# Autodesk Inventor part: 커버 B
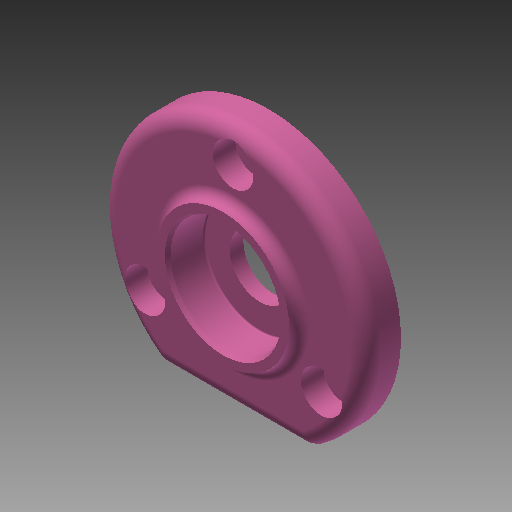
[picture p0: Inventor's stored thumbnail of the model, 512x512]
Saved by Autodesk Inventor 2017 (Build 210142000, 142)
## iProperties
Created: 2020-04
Part Number: 커버 B
Material: 알루미늄 6061
Document SubType Name: Modeling
Designer: mduedu
Density: 1 g/cm^3
Appearance: 분홍색
Author: mduedu
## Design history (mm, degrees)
sketch "스케치1"
  geometry: C1 r 26 at (0, 0); 1 further point
  constraints: 1 centre point, 1 coincident
  dimensions: "d0" = 52 diameter of C1
extrude "돌출1" new body sketch "스케치1" distance "d1" = 7; taper "d2" = 0 deg
sketch "스케치2"
  geometry: L1 (-14.62, -21.5)-(14.62, -21.5); A1 r 26 centre (0, 0) between (-14.62, -21.5) and (14.62, -21.5) reference; 1 further point
  constraints: 2 end point, 2 point on circle, 1 horizontal
  dimensions: "d3" = 21.5 distance from line of L1 point (0, 0)
extrude "돌출2" cut sketch "스케치2" stored distance "d4" = 7; taper "d5" = 0 deg
sketch "스케치6"
  geometry: C1 r 13 at (0, 0); 1 further point
  constraints: 1 centre point, 1 coincident
  dimensions: "d29" = 26 diameter of C1
extrude "돌출5" join sketch "스케치6" distance "d30" = 2; taper "d31" = 0 deg
fillet "모깎기1" dims "d6" = 3
fillet "모깎기2" dims "d7" = 3
fillet "모깎기4" dims "d33" = 2
sketch "스케치3" dims "d8" = 40
  geometry: 3 further points
  constraints: 2 vertical alignment, 1 coincident, 2 other
hole "구멍1" sketch "스케치3" at (0, 20) diameter "d9" = 4.5; stored, may be unused: countersink angle "d13" = 90 deg, drill point angle "d15" = 118 deg; dims "d10" = 6, "d11" = 8, "d12" = 4.4, "d14" = 8
sketch "스케치4"
  geometry: C1 r 14 at (0, 0); 1 further point
  constraints: 1 centre point, 1 coincident
  dimensions: "d19" = 28 diameter of C1
extrude "돌출3" join sketch "스케치4" distance "d20" = 4; taper "d21" = 0 deg
sketch "스케치5"
  geometry: C1 r 12 at (0, 0); 1 further point
  constraints: 1 centre point, 1 coincident
  dimensions: "d22" = 24 diameter of C1
extrude "돌출4" cut sketch "스케치5" distance "d23" = 3; taper "d24" = 0 deg
fillet "모깎기3" dims "d25" = 3
chamfer "모따기1" distance "d26" = 0.5; stored, may be unused: second distance "d27" = 2, angle "d28" = 45 deg
sketch "스케치7"
  geometry: 2 further points
  constraints: 1 coincident
hole "구멍2" sketch "스케치7" at (0, 0) diameter "d34" = 12; stored, may be unused: countersink angle "d38" = 90 deg, drill point angle "d40" = 118 deg; dims "d35" = 6, "d36" = 22, "d37" = 7.3, "d39" = 8
fillet "모깎기5" dims "d41" = 0.3
chamfer "모따기2" distance "d42" = 0.7; stored, may be unused: second distance "d43" = 2, angle "d44" = 30 deg
node "솔리드1"
pattern_circular "원형 패턴1" dims angle "d17" = 360 deg
node "투영된 루프1"
